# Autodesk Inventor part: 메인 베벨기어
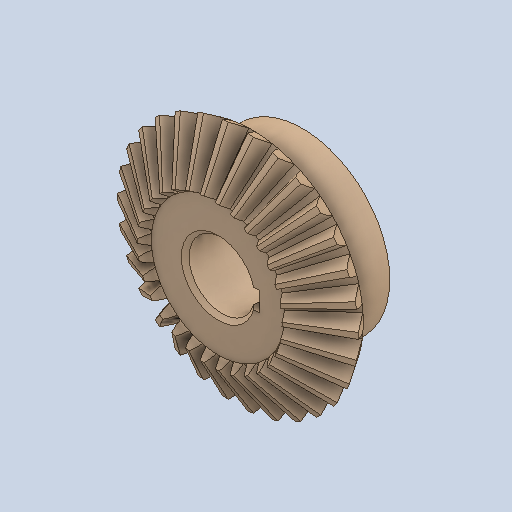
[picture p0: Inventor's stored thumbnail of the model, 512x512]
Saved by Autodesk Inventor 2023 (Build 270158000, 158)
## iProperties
Created: 2025-04
Part Number: 메인 베벨기어
Material: 강철, 탄소
Document SubType Name: Modeling
Designer: ADMIN_PC
Density: 7.87 g/cm^3
Appearance: 기본값
Author: jhkim
Revision Number: 1
Sending System: Autodesk Inventor 2026
Preprocessor: ST-DEVELOPER v20.1
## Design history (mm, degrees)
feature "Solid1"
node "솔리드1"
